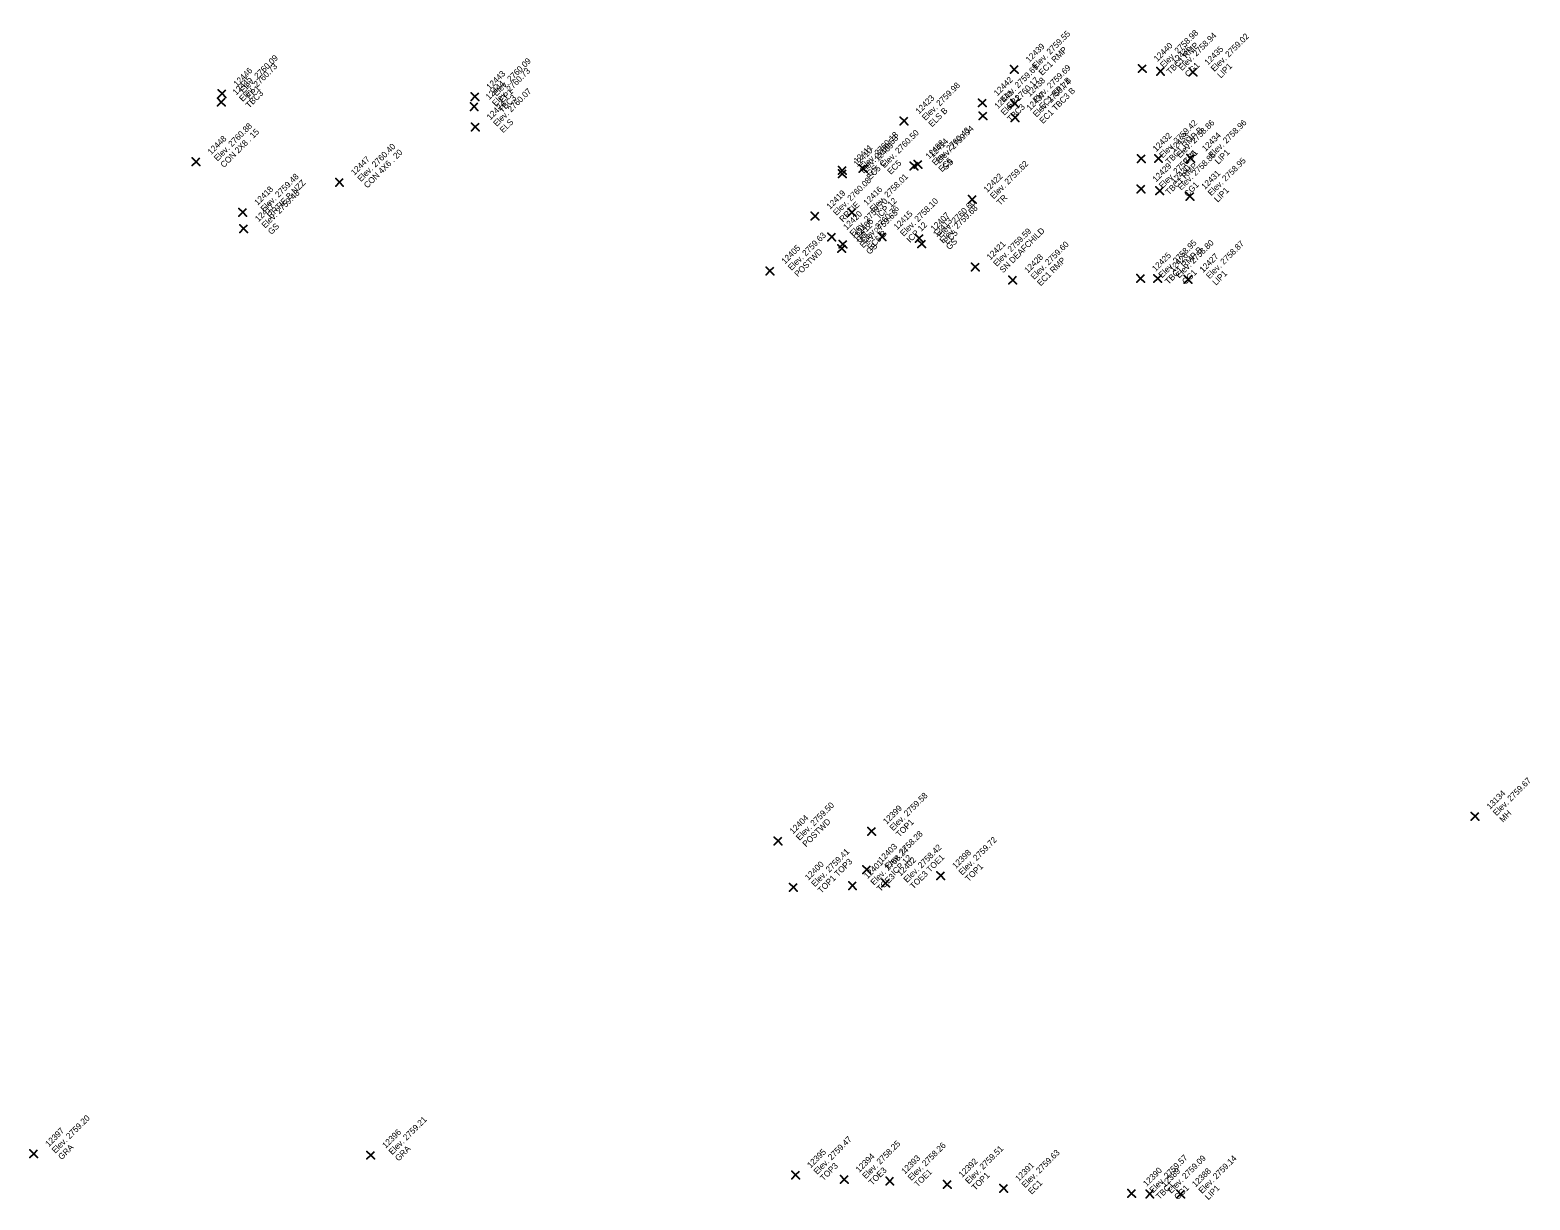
# Model space of a CAD drawing. Extents: x 2493999 to 2503109, y 700767 to 706646.
# Drawn here: x 2502205.1 to 2502264.4, y 702244.9 to 702291.1 of the extents above; entities that cross this region are included whole.
import ezdxf

# ---------------------------------------------------------------- set-up
doc = ezdxf.new("R2010")
doc.units = 0
doc.layers.add('ALG_CL_BLUE_Horiz', color=7, linetype='Continuous')
doc.layers.add('DES_SURFACE_Existing-Ground', color=7, linetype='Continuous')

msp = doc.modelspace()

# ---------------------------------------------------------------- linework, layer by layer
at = {"layer": 'ALG_CL_BLUE_Horiz'}
for points in [[(2502244, 702289.57), (2502243.85, 702289.72), (2502244, 702289.57), (2502243.85, 702289.42), (2502244, 702289.57), (2502244.15, 702289.42), (2502244, 702289.57), (2502244.15, 702289.72)], [(2502249.059, 702289.605), (2502248.909, 702289.755), (2502249.059, 702289.605), (2502248.909, 702289.455), (2502249.059, 702289.605), (2502249.209, 702289.455), (2502249.059, 702289.605), (2502249.209, 702289.755)], [(2502249.78, 702289.499), (2502249.63, 702289.649), (2502249.78, 702289.499), (2502249.63, 702289.349), (2502249.78, 702289.499), (2502249.93, 702289.349), (2502249.78, 702289.499), (2502249.93, 702289.649)], [(2502251.064, 702289.464), (2502250.914, 702289.614), (2502251.064, 702289.464), (2502250.914, 702289.314), (2502251.064, 702289.464), (2502251.214, 702289.314), (2502251.064, 702289.464), (2502251.214, 702289.614)], [(2502212.646, 702288.279), (2502212.496, 702288.429), (2502212.646, 702288.279), (2502212.496, 702288.129), (2502212.646, 702288.279), (2502212.796, 702288.129), (2502212.646, 702288.279), (2502212.796, 702288.429)], [(2502212.676, 702288.614), (2502212.526, 702288.764), (2502212.676, 702288.614), (2502212.526, 702288.464), (2502212.676, 702288.614), (2502212.826, 702288.464), (2502212.676, 702288.614), (2502212.826, 702288.764)], [(2502222.675, 702288.493), (2502222.525, 702288.643), (2502222.675, 702288.493), (2502222.525, 702288.343), (2502222.675, 702288.493), (2502222.825, 702288.343), (2502222.675, 702288.493), (2502222.825, 702288.643)], [(2502242.738, 702288.249), (2502242.588, 702288.399), (2502242.738, 702288.249), (2502242.588, 702288.099), (2502242.738, 702288.249), (2502242.888, 702288.099), (2502242.738, 702288.249), (2502242.888, 702288.399)], [(2502244.018, 702288.225), (2502243.868, 702288.375), (2502244.018, 702288.225), (2502243.868, 702288.075), (2502244.018, 702288.225), (2502244.168, 702288.075), (2502244.018, 702288.225), (2502244.168, 702288.375)], [(2502222.645, 702288.099), (2502222.495, 702288.249), (2502222.645, 702288.099), (2502222.495, 702287.949), (2502222.645, 702288.099), (2502222.795, 702287.949), (2502222.645, 702288.099), (2502222.795, 702288.249)], [(2502239.64, 702287.531), (2502239.49, 702287.681), (2502239.64, 702287.531), (2502239.49, 702287.381), (2502239.64, 702287.531), (2502239.79, 702287.381), (2502239.64, 702287.531), (2502239.79, 702287.681)], [(2502242.76, 702287.736), (2502242.61, 702287.886), (2502242.76, 702287.736), (2502242.61, 702287.586), (2502242.76, 702287.736), (2502242.91, 702287.586), (2502242.76, 702287.736), (2502242.91, 702287.886)], [(2502244.028, 702287.663), (2502243.878, 702287.813), (2502244.028, 702287.663), (2502243.878, 702287.513), (2502244.028, 702287.663), (2502244.178, 702287.513), (2502244.028, 702287.663), (2502244.178, 702287.813)], [(2502222.691, 702287.295), (2502222.541, 702287.445), (2502222.691, 702287.295), (2502222.541, 702287.145), (2502222.691, 702287.295), (2502222.841, 702287.145), (2502222.691, 702287.295), (2502222.841, 702287.445)], [(2502211.65, 702285.923), (2502211.5, 702286.073), (2502211.65, 702285.923), (2502211.5, 702285.773), (2502211.65, 702285.923), (2502211.8, 702285.773), (2502211.65, 702285.923), (2502211.8, 702286.073)], [(2502240.036, 702285.752), (2502239.886, 702285.902), (2502240.036, 702285.752), (2502239.886, 702285.602), (2502240.036, 702285.752), (2502240.186, 702285.602), (2502240.036, 702285.752), (2502240.186, 702285.902)], [(2502240.188, 702285.821), (2502240.038, 702285.971), (2502240.188, 702285.821), (2502240.038, 702285.671), (2502240.188, 702285.821), (2502240.338, 702285.671), (2502240.188, 702285.821), (2502240.338, 702285.971)], [(2502249.019, 702286.044), (2502248.869, 702286.194), (2502249.019, 702286.044), (2502248.869, 702285.894), (2502249.019, 702286.044), (2502249.169, 702285.894), (2502249.019, 702286.044), (2502249.169, 702286.194)], [(2502249.703, 702286.048), (2502249.553, 702286.198), (2502249.703, 702286.048), (2502249.553, 702285.898), (2502249.703, 702286.048), (2502249.853, 702285.898), (2502249.703, 702286.048), (2502249.853, 702286.198)], [(2502250.969, 702286.055), (2502250.819, 702286.205), (2502250.969, 702286.055), (2502250.819, 702285.905), (2502250.969, 702286.055), (2502251.119, 702285.905), (2502250.969, 702286.055), (2502251.119, 702286.205)], [(2502237.197, 702285.445), (2502237.047, 702285.595), (2502237.197, 702285.445), (2502237.047, 702285.295), (2502237.197, 702285.445), (2502237.347, 702285.295), (2502237.197, 702285.445), (2502237.347, 702285.595)], [(2502237.198, 702285.576), (2502237.048, 702285.726), (2502237.198, 702285.576), (2502237.048, 702285.426), (2502237.198, 702285.576), (2502237.348, 702285.426), (2502237.198, 702285.576), (2502237.348, 702285.726)], [(2502238.015, 702285.654), (2502237.865, 702285.804), (2502238.015, 702285.654), (2502237.865, 702285.504), (2502238.015, 702285.654), (2502238.165, 702285.504), (2502238.015, 702285.654), (2502238.165, 702285.804)], [(2502217.32, 702285.111), (2502217.17, 702285.261), (2502217.32, 702285.111), (2502217.17, 702284.961), (2502217.32, 702285.111), (2502217.47, 702284.961), (2502217.32, 702285.111), (2502217.47, 702285.261)], [(2502249.011, 702284.844), (2502248.861, 702284.994), (2502249.011, 702284.844), (2502248.861, 702284.694), (2502249.011, 702284.844), (2502249.161, 702284.694), (2502249.011, 702284.844), (2502249.161, 702284.994)], [(2502249.75, 702284.772), (2502249.6, 702284.922), (2502249.75, 702284.772), (2502249.6, 702284.622), (2502249.75, 702284.772), (2502249.9, 702284.622), (2502249.75, 702284.772), (2502249.9, 702284.922)], [(2502242.338, 702284.431), (2502242.188, 702284.581), (2502242.338, 702284.431), (2502242.188, 702284.281), (2502242.338, 702284.431), (2502242.488, 702284.281), (2502242.338, 702284.431), (2502242.488, 702284.581)], [(2502250.942, 702284.554), (2502250.792, 702284.704), (2502250.942, 702284.554), (2502250.792, 702284.404), (2502250.942, 702284.554), (2502251.092, 702284.404), (2502250.942, 702284.554), (2502251.092, 702284.704)], [(2502213.497, 702283.924), (2502213.347, 702284.074), (2502213.497, 702283.924), (2502213.347, 702283.774), (2502213.497, 702283.924), (2502213.647, 702283.774), (2502213.497, 702283.924), (2502213.647, 702284.074)], [(2502236.122, 702283.771), (2502235.972, 702283.921), (2502236.122, 702283.771), (2502235.972, 702283.621), (2502236.122, 702283.771), (2502236.272, 702283.621), (2502236.122, 702283.771), (2502236.272, 702283.921)], [(2502237.583, 702283.917), (2502237.433, 702284.067), (2502237.583, 702283.917), (2502237.433, 702283.767), (2502237.583, 702283.917), (2502237.733, 702283.767), (2502237.583, 702283.917), (2502237.733, 702284.067)], [(2502213.529, 702283.275), (2502213.379, 702283.425), (2502213.529, 702283.275), (2502213.379, 702283.125), (2502213.529, 702283.275), (2502213.679, 702283.125), (2502213.529, 702283.275), (2502213.679, 702283.425)], [(2502236.782, 702282.95), (2502236.632, 702283.1), (2502236.782, 702282.95), (2502236.632, 702282.8), (2502236.782, 702282.95), (2502236.932, 702282.8), (2502236.782, 702282.95), (2502236.932, 702283.1)], [(2502238.777, 702282.956), (2502238.627, 702283.106), (2502238.777, 702282.956), (2502238.627, 702282.806), (2502238.777, 702282.956), (2502238.927, 702282.806), (2502238.777, 702282.956), (2502238.927, 702283.106)], [(2502240.243, 702282.893), (2502240.093, 702283.043), (2502240.243, 702282.893), (2502240.093, 702282.743), (2502240.243, 702282.893), (2502240.393, 702282.743), (2502240.243, 702282.893), (2502240.393, 702283.043)], [(2502237.179, 702282.491), (2502237.029, 702282.641), (2502237.179, 702282.491), (2502237.029, 702282.341), (2502237.179, 702282.491), (2502237.329, 702282.341), (2502237.179, 702282.491), (2502237.329, 702282.641)], [(2502237.226, 702282.663), (2502237.076, 702282.813), (2502237.226, 702282.663), (2502237.076, 702282.513), (2502237.226, 702282.663), (2502237.376, 702282.513), (2502237.226, 702282.663), (2502237.376, 702282.813)], [(2502240.338, 702282.676), (2502240.188, 702282.826), (2502240.338, 702282.676), (2502240.188, 702282.526), (2502240.338, 702282.676), (2502240.488, 702282.526), (2502240.338, 702282.676), (2502240.488, 702282.826)], [(2502234.341, 702281.602), (2502234.191, 702281.752), (2502234.341, 702281.602), (2502234.191, 702281.452), (2502234.341, 702281.602), (2502234.491, 702281.452), (2502234.341, 702281.602), (2502234.491, 702281.752)], [(2502242.457, 702281.762), (2502242.307, 702281.912), (2502242.457, 702281.762), (2502242.307, 702281.612), (2502242.457, 702281.762), (2502242.607, 702281.612), (2502242.457, 702281.762), (2502242.607, 702281.912)], [(2502243.94, 702281.245), (2502243.79, 702281.395), (2502243.94, 702281.245), (2502243.79, 702281.095), (2502243.94, 702281.245), (2502244.09, 702281.095), (2502243.94, 702281.245), (2502244.09, 702281.395)], [(2502248.995, 702281.308), (2502248.845, 702281.458), (2502248.995, 702281.308), (2502248.845, 702281.158), (2502248.995, 702281.308), (2502249.145, 702281.158), (2502248.995, 702281.308), (2502249.145, 702281.458)], [(2502249.67, 702281.304), (2502249.52, 702281.454), (2502249.67, 702281.304), (2502249.52, 702281.154), (2502249.67, 702281.304), (2502249.82, 702281.154), (2502249.67, 702281.304), (2502249.82, 702281.454)], [(2502250.87, 702281.268), (2502250.72, 702281.418), (2502250.87, 702281.268), (2502250.72, 702281.118), (2502250.87, 702281.268), (2502251.02, 702281.118), (2502250.87, 702281.268), (2502251.02, 702281.418)], [(2502262.218, 702260.046), (2502262.068, 702260.196), (2502262.218, 702260.046), (2502262.068, 702259.896), (2502262.218, 702260.046), (2502262.368, 702259.896), (2502262.218, 702260.046), (2502262.368, 702260.196)], [(2502234.662, 702259.073), (2502234.512, 702259.223), (2502234.662, 702259.073), (2502234.512, 702258.923), (2502234.662, 702259.073), (2502234.812, 702258.923), (2502234.662, 702259.073), (2502234.812, 702259.223)], [(2502238.358, 702259.453), (2502238.208, 702259.603), (2502238.358, 702259.453), (2502238.208, 702259.303), (2502238.358, 702259.453), (2502238.508, 702259.303), (2502238.358, 702259.453), (2502238.508, 702259.603)], [(2502238.167, 702257.94), (2502238.017, 702258.09), (2502238.167, 702257.94), (2502238.017, 702257.79), (2502238.167, 702257.94), (2502238.317, 702257.79), (2502238.167, 702257.94), (2502238.317, 702258.09)], [(2502237.604, 702257.303), (2502237.454, 702257.453), (2502237.604, 702257.303), (2502237.454, 702257.153), (2502237.604, 702257.303), (2502237.754, 702257.153), (2502237.604, 702257.303), (2502237.754, 702257.453)], [(2502238.91, 702257.407), (2502238.76, 702257.557), (2502238.91, 702257.407), (2502238.76, 702257.257), (2502238.91, 702257.407), (2502239.06, 702257.257), (2502238.91, 702257.407), (2502239.06, 702257.557)], [(2502241.093, 702257.701), (2502240.943, 702257.851), (2502241.093, 702257.701), (2502240.943, 702257.551), (2502241.093, 702257.701), (2502241.243, 702257.551), (2502241.093, 702257.701), (2502241.243, 702257.851)], [(2502235.267, 702257.239), (2502235.117, 702257.389), (2502235.267, 702257.239), (2502235.117, 702257.089), (2502235.267, 702257.239), (2502235.417, 702257.089), (2502235.267, 702257.239), (2502235.417, 702257.389)], [(2502205.234, 702246.704), (2502205.084, 702246.854), (2502205.234, 702246.704), (2502205.084, 702246.554), (2502205.234, 702246.704), (2502205.384, 702246.554), (2502205.234, 702246.704), (2502205.384, 702246.854)], [(2502218.556, 702246.648), (2502218.406, 702246.798), (2502218.556, 702246.648), (2502218.406, 702246.498), (2502218.556, 702246.648), (2502218.706, 702246.498), (2502218.556, 702246.648), (2502218.706, 702246.798)], [(2502235.356, 702245.866), (2502235.206, 702246.016), (2502235.356, 702245.866), (2502235.206, 702245.716), (2502235.356, 702245.866), (2502235.506, 702245.716), (2502235.356, 702245.866), (2502235.506, 702246.016)], [(2502237.279, 702245.693), (2502237.129, 702245.843), (2502237.279, 702245.693), (2502237.129, 702245.543), (2502237.279, 702245.693), (2502237.429, 702245.543), (2502237.279, 702245.693), (2502237.429, 702245.843)], [(2502239.078, 702245.623), (2502238.928, 702245.773), (2502239.078, 702245.623), (2502238.928, 702245.473), (2502239.078, 702245.623), (2502239.228, 702245.473), (2502239.078, 702245.623), (2502239.228, 702245.773)], [(2502241.35, 702245.494), (2502241.2, 702245.644), (2502241.35, 702245.494), (2502241.2, 702245.344), (2502241.35, 702245.494), (2502241.5, 702245.344), (2502241.35, 702245.494), (2502241.5, 702245.644)], [(2502243.584, 702245.34), (2502243.434, 702245.49), (2502243.584, 702245.34), (2502243.434, 702245.19), (2502243.584, 702245.34), (2502243.734, 702245.19), (2502243.584, 702245.34), (2502243.734, 702245.49)], [(2502248.638, 702245.136), (2502248.488, 702245.286), (2502248.638, 702245.136), (2502248.488, 702244.986), (2502248.638, 702245.136), (2502248.788, 702244.986), (2502248.638, 702245.136), (2502248.788, 702245.286)], [(2502249.359, 702245.117), (2502249.209, 702245.267), (2502249.359, 702245.117), (2502249.209, 702244.967), (2502249.359, 702245.117), (2502249.509, 702244.967), (2502249.359, 702245.117), (2502249.509, 702245.267)], [(2502250.574, 702245.113), (2502250.424, 702245.263), (2502250.574, 702245.113), (2502250.424, 702244.963), (2502250.574, 702245.113), (2502250.724, 702244.963), (2502250.574, 702245.113), (2502250.724, 702245.263)]]:
    msp.add_lwpolyline(points, dxfattribs=at)

# ---------------------------------------------------------------- texts
at = {"layer": 'DES_SURFACE_Existing-Ground'}
for s, p in [('Elev. 2759.55', (2502244.849, 702289.57)), ('Elev. 2758.98', (2502249.908, 702289.605)), ('Elev. 2758.94', (2502250.629, 702289.499)), ('Elev. 2759.02', (2502251.913, 702289.464)), ('Elev. 2760.09', (2502213.525, 702288.614)), ('12439', (2502244.594, 702289.825)), ('EC1 RMP', (2502245.103, 702289.315)), ('12440', (2502249.653, 702289.86)), ('TBC1 RMP', (2502250.162, 702289.35)), ('12436', (2502250.374, 702289.754)), ('12435', (2502251.658, 702289.719)), ('12446', (2502213.27, 702288.869)), ('Elev. 2760.73', (2502213.495, 702288.279)), ('12443', (2502223.269, 702288.748)), ('Elev. 2760.73', (2502223.494, 702288.099)), ('Elev. 2760.09', (2502223.524, 702288.493)), ('Elev. 2759.69', (2502243.587, 702288.249)), ('Elev. 2759.69', (2502244.867, 702288.225)), ('CG1', (2502250.883, 702289.244)), ('LIP1', (2502252.167, 702289.209)), ('12445', (2502213.24, 702288.534)), ('EP1', (2502213.779, 702288.359)), ('12444', (2502223.239, 702288.354)), ('Elev. 2759.98', (2502240.489, 702287.531)), ('12442', (2502243.332, 702288.504)), ('Elev. 2760.17', (2502243.609, 702287.736)), ('12438', (2502244.612, 702288.48)), ('Elev. 2759.74', (2502244.877, 702287.663)), ('EC1 EP1 B', (2502245.121, 702287.97)), ('TBC3', (2502213.749, 702288.024)), ('12424', (2502223.285, 702287.55)), ('Elev. 2760.07', (2502223.54, 702287.295)), ('TBC3', (2502223.748, 702287.844)), ('EP1', (2502223.778, 702288.238)), ('12423', (2502240.234, 702287.786)), ('12441', (2502243.354, 702287.991)), ('EP1', (2502243.841, 702287.994)), ('12437', (2502244.622, 702287.918)), ('EC1 TBC3 B', (2502245.131, 702287.408)), ('ELS B', (2502240.743, 702287.276)), ('TBC3', (2502243.863, 702287.481)), ('Elev. 2760.88', (2502212.499, 702285.923)), ('CON 2X8 . 15', (2502212.753, 702285.668)), ('ELS', (2502223.794, 702287.04)), ('Elev. 2760.18', (2502238.047, 702285.576)), ('Elev. 2760.50', (2502238.864, 702285.654)), ('Elev. 2760.43', (2502240.885, 702285.752)), ('Elev. 2759.94', (2502241.037, 702285.821)), ('Elev. 2759.42', (2502249.868, 702286.044)), ('TBC1 RMP B', (2502250.122, 702285.789)), ('Elev. 2758.86', (2502250.552, 702286.048)), ('Elev. 2758.96', (2502251.818, 702286.055)), ('12448', (2502212.244, 702286.178)), ('Elev. 2760.40', (2502218.169, 702285.111)), ('12411', (2502237.792, 702285.831)), ('Elev. 2760.53', (2502238.046, 702285.445)), ('12409', (2502238.609, 702285.909)), ('12408', (2502240.63, 702286.007)), ('12414', (2502240.782, 702286.076)), ('12432', (2502249.613, 702286.299)), ('12433', (2502250.297, 702286.303)), ('12434', (2502251.563, 702286.31)), ('12447', (2502217.914, 702285.366)), ('CON 4X6 . 20', (2502218.423, 702284.856)), ('12410', (2502237.791, 702285.7)), ('EC5 C', (2502238.3, 702285.19)), ('EC5', (2502239.118, 702285.399)), ('EC5', (2502241.139, 702285.497)), ('GS', (2502241.291, 702285.566)), ('Elev. 2759.62', (2502243.187, 702284.431)), ('Elev. 2759.35', (2502249.86, 702284.844)), ('Elev. 2758.86', (2502250.599, 702284.772)), ('CG1', (2502250.806, 702285.793)), ('Elev. 2758.95', (2502251.791, 702284.554)), ('LIP1', (2502252.072, 702285.8)), ('Elev. 2759.48', (2502214.346, 702283.924)), ('GS', (2502238.301, 702285.321)), ('Elev. 2758.01', (2502238.432, 702283.917)), ('12422', (2502242.932, 702284.686)), ('12429', (2502249.605, 702285.099)), ('TBC1 RMP', (2502250.114, 702284.589)), ('12430', (2502250.344, 702285.027)), ('12431', (2502251.536, 702284.809)), ('12418', (2502214.091, 702284.179)), ('Elev. 2759.48', (2502214.378, 702283.275)), ('RRTIE B NZZ', (2502214.6, 702283.669)), ('12419', (2502236.716, 702284.026)), ('Elev. 2760.08', (2502236.971, 702283.771)), ('12416', (2502238.177, 702284.172)), ('CG1', (2502250.853, 702284.517)), ('LIP1', (2502252.045, 702284.299)), ('12417', (2502214.123, 702283.53)), ('RRTIE', (2502237.225, 702283.516)), ('Elev. 2759.70', (2502237.631, 702282.95)), ('Elev. 2760.76', (2502238.075, 702282.663)), ('ICP 12', (2502238.686, 702283.662)), ('Elev. 2758.10', (2502239.626, 702282.956)), ('Elev. 2760.60', (2502241.092, 702282.893)), ('Elev. 2759.68', (2502241.187, 702282.676)), ('TR', (2502243.441, 702284.176)), ('12420', (2502237.376, 702283.205)), ('12406', (2502237.82, 702282.918)), ('Elev. 2759.63', (2502238.028, 702282.491)), ('12415', (2502239.371, 702283.211)), ('ICP 12', (2502239.88, 702282.701)), ('12407', (2502240.837, 702283.148)), ('12413', (2502240.932, 702282.931)), ('GS', (2502214.632, 702283.02)), ('Elev. 2759.63', (2502235.19, 702281.602)), ('12412', (2502237.773, 702282.746)), ('GS', (2502237.885, 702282.695)), ('EC5 B', (2502238.329, 702282.408)), ('EC5', (2502241.346, 702282.638)), ('Elev. 2759.59', (2502243.306, 702281.762)), ('SN DEAFCHILD', (2502243.56, 702281.507)), ('12405', (2502234.935, 702281.857)), ('POSTWD', (2502235.444, 702281.347)), ('GS', (2502238.282, 702282.236)), ('GS', (2502241.441, 702282.421)), ('12421', (2502243.051, 702282.017)), ('Elev. 2759.60', (2502244.789, 702281.245)), ('12425', (2502249.589, 702281.563)), ('Elev. 2758.95', (2502249.844, 702281.308)), ('TBC1 RMP B', (2502250.098, 702281.053)), ('12426', (2502250.264, 702281.559)), ('Elev. 2758.80', (2502250.519, 702281.304)), ('Elev. 2758.87', (2502251.719, 702281.268)), ('12428', (2502244.534, 702281.5)), ('EC1 RMP', (2502245.043, 702280.99)), ('12427', (2502251.464, 702281.523)), ('CG1', (2502250.773, 702281.049)), ('LIP1', (2502251.973, 702281.013)), ('Elev. 2759.67', (2502263.067, 702260.046)), ('13134', (2502262.812, 702260.301)), ('Elev. 2759.50', (2502235.511, 702259.073)), ('12399', (2502238.952, 702259.708)), ('Elev. 2759.58', (2502239.207, 702259.453)), ('12404', (2502235.256, 702259.328)), ('POSTWD', (2502235.765, 702258.818)), ('TOP1', (2502239.461, 702259.198)), ('MH', (2502263.321, 702259.791)), ('Elev. 2758.28', (2502239.016, 702257.94)), ('Elev. 2759.72', (2502241.942, 702257.701)), ('Elev. 2759.41', (2502236.116, 702257.239)), ('Elev. 2758.24', (2502238.453, 702257.303)), ('12403', (2502238.761, 702258.195)), ('Elev. 2758.42', (2502239.759, 702257.407)), ('12398', (2502241.687, 702257.956)), ('12400', (2502235.861, 702257.494)), ('TOP1 TOP3', (2502236.37, 702256.984)), ('12401', (2502238.198, 702257.558)), ('ICP 12', (2502239.27, 702257.685)), ('12402', (2502239.504, 702257.662)), ('TOE3 TOE1', (2502240.013, 702257.152)), ('TOP1', (2502242.196, 702257.446)), ('TOE3', (2502238.707, 702257.048)), ('Elev. 2759.20', (2502206.083, 702246.704)), ('Elev. 2759.21', (2502219.405, 702246.648)), ('12397', (2502205.828, 702246.959)), ('12396', (2502219.15, 702246.903)), ('Elev. 2759.47', (2502236.205, 702245.866)), ('GRA', (2502206.337, 702246.449)), ('GRA', (2502219.659, 702246.393)), ('12395', (2502235.95, 702246.121)), ('Elev. 2758.25', (2502238.128, 702245.693)), ('Elev. 2758.26', (2502239.927, 702245.623)), ('Elev. 2759.51', (2502242.199, 702245.494)), ('Elev. 2759.63', (2502244.433, 702245.34)), ('TOP3', (2502236.459, 702245.611)), ('12394', (2502237.873, 702245.948)), ('TOE3', (2502238.382, 702245.438)), ('12393', (2502239.672, 702245.878)), ('12392', (2502241.944, 702245.749)), ('12391', (2502244.178, 702245.595)), ('Elev. 2759.57', (2502249.487, 702245.136)), ('Elev. 2759.09', (2502250.208, 702245.117)), ('Elev. 2759.14', (2502251.423, 702245.113)), ('TOE1', (2502240.181, 702245.368)), ('TOP1', (2502242.453, 702245.239)), ('EC1', (2502244.687, 702245.085)), ('12390', (2502249.232, 702245.391)), ('TBC1', (2502249.741, 702244.881)), ('12389', (2502249.953, 702245.372)), ('12388', (2502251.168, 702245.368)), ('CG1', (2502250.462, 702244.862)), ('LIP1', (2502251.677, 702244.858))]:
    msp.add_text(s, height=0.24, rotation=45, dxfattribs=at).set_placement(p)

doc.saveas('drawing.dxf')
